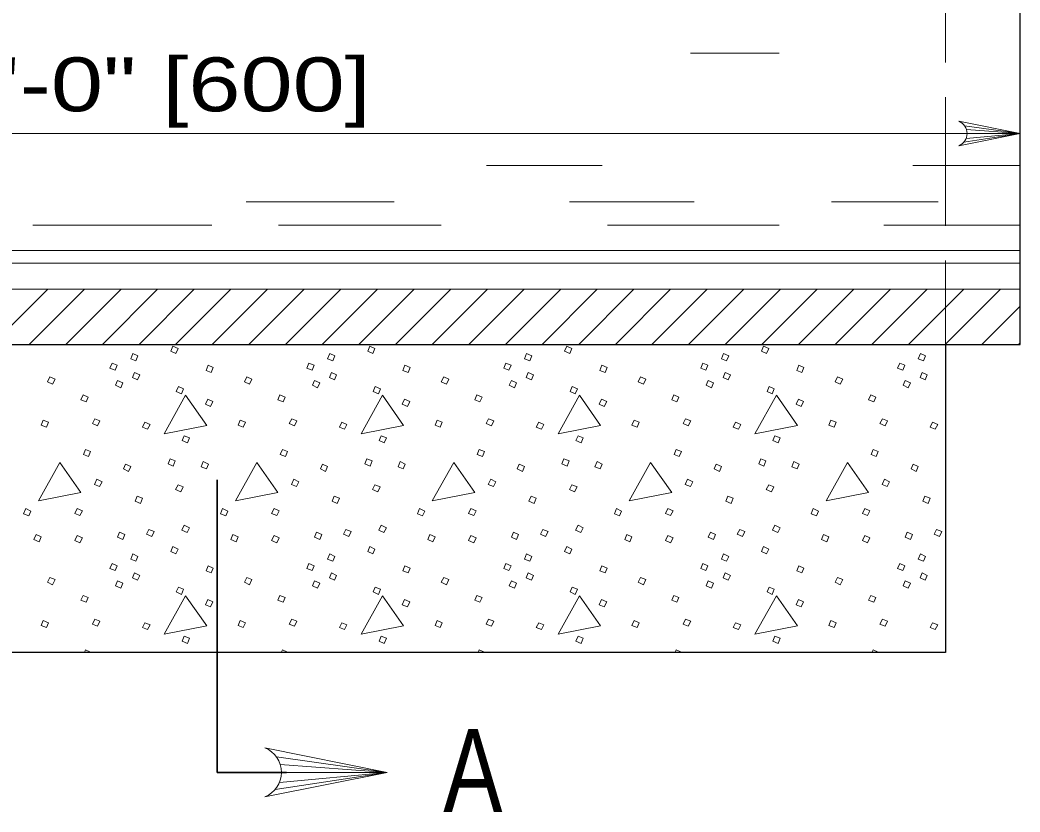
# Model space of a CAD drawing. Extents: x 1036.7 to 1070.7, y 883.9 to 905.9.
# Drawn here: x 1047.274 to 1050.167, y 893.349 to 895.639 of the extents above; entities that cross this region are included whole.
import ezdxf

# ---------------------------------------------------------------- set-up
doc = ezdxf.new("R2010")
doc.units = 0
doc.header["$LTSCALE"] = 0.062
doc.linetypes.add('LONG_DASHED', pattern=[7.5, 6, -1.5])
doc.layers.add('1', color=7, linetype='Continuous', lineweight=13)

msp = doc.modelspace()

# ---------------------------------------------------------------- linework, layer by layer
at = {"layer": '1', "linetype": 'LONG_DASHED'}
msp.add_line((1049.95158, 896.83225), (1049.95158, 894.70125), dxfattribs=at)
at = {"layer": '1', "lineweight": 25}
for p, q in [((1050.167, 894.86117), (1050.167, 896.67133)), ((1050.167, 894.70125), (1050.167, 894.86117)), ((1046.47158, 894.70125), (1050.167, 894.70125)), ((1049.95158, 894.70125), (1049.95158, 893.80992)), ((1049.00467, 893.80992), (1045.73742, 893.80992)), ((1049.95158, 893.80992), (1048.87233, 893.80992))]:
    msp.add_line(p, q, dxfattribs=at)
at = {"layer": '1'}
for p, q in [((1049.21367, 895.54308), (1049.46975, 895.54308)), ((1045.94308, 895.31108), (1048.23675, 895.31108)), ((1048.23675, 895.31108), (1050.167, 895.31108)), ((1050.00492, 895.28625), (1050.167, 895.31108)), ((1050.00675, 895.3335), (1050.167, 895.31108)), ((1050.011, 895.29667), (1050.167, 895.31108)), ((1050.01217, 895.32233), (1050.167, 895.31108)), ((1050.01383, 895.31108), (1050.167, 895.31108)), ((1048.62308, 895.2185), (1048.95758, 895.2185)), ((1049.85658, 895.2185), (1050.167, 895.2185)), ((1047.92792, 895.11383), (1048.35642, 895.11383)), ((1048.8635, 895.11383), (1049.22417, 895.11383)), ((1049.62133, 895.11383), (1049.92975, 895.11383)), ((1047.31108, 895.04575), (1047.82858, 895.04575)), ((1048.02192, 895.04575), (1048.49242, 895.04575)), ((1048.97325, 895.04575), (1049.46975, 895.04575)), ((1049.77292, 895.04575), (1050.167, 895.04575)), ((1045.94308, 894.97258), (1050.167, 894.97258)), ((1045.94308, 894.93592), (1050.167, 894.93592)), ((1050.167, 894.86117), (1045.94308, 894.86117)), ((1047.19383, 894.70125), (1047.35375, 894.86117)), ((1047.29983, 894.70125), (1047.45983, 894.86117)), ((1047.40592, 894.70125), (1047.56583, 894.86117)), ((1047.51192, 894.70125), (1047.67183, 894.86117)), ((1047.618, 894.70125), (1047.77792, 894.86117)), ((1047.72392, 894.70125), (1047.88383, 894.86117)), ((1047.82992, 894.70125), (1047.98992, 894.86117)), ((1047.936, 894.70125), (1048.09592, 894.86117)), ((1048.042, 894.70125), (1048.20192, 894.86117)), ((1048.14808, 894.70125), (1048.308, 894.86117)), ((1048.254, 894.70125), (1048.41392, 894.86117)), ((1048.36, 894.70125), (1048.52, 894.86117)), ((1048.46608, 894.70125), (1048.626, 894.86117)), ((1048.57208, 894.70125), (1048.732, 894.86117)), ((1048.67817, 894.70125), (1048.83808, 894.86117)), ((1048.78408, 894.70125), (1048.944, 894.86117)), ((1048.89008, 894.70125), (1049.05008, 894.86117)), ((1048.99617, 894.70125), (1049.15608, 894.86117)), ((1049.10217, 894.70125), (1049.26208, 894.86117)), ((1049.20825, 894.70125), (1049.36817, 894.86117)), ((1049.31417, 894.70125), (1049.47408, 894.86117)), ((1049.42017, 894.70125), (1049.58017, 894.86117)), ((1049.52625, 894.70125), (1049.68617, 894.86117)), ((1049.63225, 894.70125), (1049.79217, 894.86117)), ((1049.73833, 894.70125), (1049.89825, 894.86117)), ((1049.84425, 894.70125), (1050.00417, 894.86117)), ((1049.95025, 894.70125), (1050.11025, 894.86117)), ((1050.05633, 894.70125), (1050.167, 894.81192)), ((1050.16233, 894.70125), (1050.167, 894.70592)), ((1047.45975, 893.80992), (1047.463, 893.81742)), ((1048.02942, 893.80992), (1048.03267, 893.81742)), ((1048.59917, 893.80992), (1048.60242, 893.81742)), ((1049.16892, 893.80992), (1049.17217, 893.81742)), ((1049.73867, 893.80992), (1049.74192, 893.81742)), ((1048.0155, 893.50825), (1048.336, 893.46342)), ((1048.01167, 893.41392), (1048.336, 893.46342)), ((1048.024, 893.43467), (1048.336, 893.46342)), ((1048.02633, 893.48608), (1048.336, 893.46342)), ((1048.02967, 893.46342), (1048.336, 893.46342))]:
    msp.add_line(p, q, dxfattribs=at)
for points in [[(1049.99, 895.27567), (1050.167, 895.31108), (1049.99, 895.34642)], [(1047.463, 893.81742), (1047.47792, 893.81142), (1047.47725, 893.80992)], [(1048.03267, 893.81742), (1048.04767, 893.81142), (1048.047, 893.80992)], [(1048.60242, 893.81742), (1048.61742, 893.81142), (1048.61675, 893.80992)], [(1049.17217, 893.81742), (1049.18717, 893.81142), (1049.1865, 893.80992)], [(1049.74192, 893.81742), (1049.75692, 893.81142), (1049.75625, 893.80992)], [(1047.982, 893.39267), (1048.336, 893.46342), (1047.982, 893.53425)]]:
    msp.add_lwpolyline(points, dxfattribs=at)
for points in [[(1047.59992, 894.67492), (1047.61492, 894.66792), (1047.60892, 894.65392), (1047.59392, 894.65992)], [(1047.71583, 894.69592), (1047.73083, 894.68892), (1047.72483, 894.67492), (1047.70983, 894.68192)], [(1048.16967, 894.67492), (1048.18458, 894.66792), (1048.17858, 894.65392), (1048.16367, 894.65992)], [(1048.28558, 894.69592), (1048.30058, 894.68892), (1048.29458, 894.67492), (1048.27958, 894.68192)], [(1048.73933, 894.67492), (1048.75433, 894.66792), (1048.74833, 894.65392), (1048.73333, 894.65992)], [(1048.85533, 894.69592), (1048.87033, 894.68892), (1048.86433, 894.67492), (1048.84933, 894.68192)], [(1049.30908, 894.67492), (1049.32408, 894.66792), (1049.31808, 894.65392), (1049.30308, 894.65992)], [(1049.425, 894.69592), (1049.44, 894.68892), (1049.434, 894.67492), (1049.419, 894.68192)], [(1049.87883, 894.67492), (1049.89383, 894.66792), (1049.88783, 894.65392), (1049.87283, 894.65992)], [(1047.53992, 894.64692), (1047.55492, 894.64092), (1047.54892, 894.62692), (1047.53392, 894.63292)], [(1048.10967, 894.64692), (1048.12467, 894.64092), (1048.11867, 894.62692), (1048.10367, 894.63292)], [(1048.67942, 894.64692), (1048.69442, 894.64092), (1048.68842, 894.62692), (1048.67342, 894.63292)], [(1049.24908, 894.64692), (1049.26408, 894.64092), (1049.25808, 894.62692), (1049.24308, 894.63292)], [(1049.81883, 894.64692), (1049.83383, 894.64092), (1049.82783, 894.62692), (1049.81283, 894.63292)], [(1047.60492, 894.61992), (1047.61992, 894.61292), (1047.61392, 894.59892), (1047.59892, 894.60592)], [(1047.81783, 894.64092), (1047.83275, 894.63392), (1047.82675, 894.61992), (1047.81183, 894.62592)], [(1048.17467, 894.61992), (1048.18958, 894.61292), (1048.18358, 894.59892), (1048.16867, 894.60592)], [(1048.3875, 894.64092), (1048.4025, 894.63392), (1048.3965, 894.61992), (1048.3815, 894.62592)], [(1048.74433, 894.61992), (1048.75933, 894.61292), (1048.75333, 894.59892), (1048.73833, 894.60592)], [(1048.95725, 894.64092), (1048.97225, 894.63392), (1048.96625, 894.61992), (1048.95125, 894.62592)], [(1049.31408, 894.61992), (1049.32908, 894.61292), (1049.32308, 894.59892), (1049.30808, 894.60592)], [(1049.527, 894.64092), (1049.542, 894.63392), (1049.536, 894.61992), (1049.521, 894.62592)], [(1049.88383, 894.61992), (1049.89883, 894.61292), (1049.89283, 894.59892), (1049.87783, 894.60592)], [(1047.36, 894.60692), (1047.375, 894.60092), (1047.368, 894.586), (1047.353, 894.59292)], [(1047.55592, 894.59692), (1047.57092, 894.58992), (1047.56492, 894.576), (1047.54992, 894.583)], [(1047.92975, 894.60692), (1047.94475, 894.60092), (1047.93775, 894.586), (1047.92275, 894.59292)], [(1048.12567, 894.59692), (1048.14067, 894.58992), (1048.13467, 894.576), (1048.11967, 894.583)], [(1048.4995, 894.60692), (1048.5145, 894.60092), (1048.5075, 894.586), (1048.4925, 894.59292)], [(1048.69542, 894.59692), (1048.71033, 894.58992), (1048.70433, 894.576), (1048.68942, 894.583)], [(1049.06917, 894.60692), (1049.08417, 894.60092), (1049.07717, 894.586), (1049.06217, 894.59292)], [(1049.26508, 894.59692), (1049.28008, 894.58992), (1049.27408, 894.576), (1049.25908, 894.583)], [(1049.63892, 894.60692), (1049.65392, 894.60092), (1049.64692, 894.586), (1049.63192, 894.59292)], [(1049.83483, 894.59692), (1049.84983, 894.58992), (1049.84383, 894.576), (1049.82883, 894.583)], [(1047.73183, 894.579), (1047.74683, 894.573), (1047.74083, 894.558), (1047.72583, 894.565)], [(1048.30158, 894.579), (1048.31658, 894.573), (1048.31058, 894.558), (1048.29558, 894.565)], [(1048.87133, 894.579), (1048.88625, 894.573), (1048.88033, 894.558), (1048.86533, 894.565)], [(1049.441, 894.579), (1049.456, 894.573), (1049.45, 894.558), (1049.435, 894.565)], [(1047.456, 894.555), (1047.47092, 894.549), (1047.46492, 894.535), (1047.45, 894.541)], [(1047.75283, 894.554), (1047.69083, 894.443), (1047.81383, 894.467)], [(1047.81683, 894.543), (1047.83175, 894.536), (1047.82475, 894.522), (1047.80983, 894.528)], [(1048.02567, 894.555), (1048.04067, 894.549), (1048.03467, 894.535), (1048.01967, 894.541)], [(1048.32258, 894.554), (1048.26058, 894.443), (1048.3835, 894.467)], [(1048.3865, 894.543), (1048.4015, 894.536), (1048.3945, 894.522), (1048.3795, 894.528)], [(1048.59542, 894.555), (1048.61042, 894.549), (1048.60442, 894.535), (1048.58942, 894.541)], [(1048.89225, 894.554), (1048.83033, 894.443), (1048.95325, 894.467)], [(1048.95625, 894.543), (1048.97125, 894.536), (1048.96425, 894.522), (1048.94925, 894.528)], [(1049.16517, 894.555), (1049.18017, 894.549), (1049.17417, 894.535), (1049.15917, 894.541)], [(1049.462, 894.554), (1049.40008, 894.443), (1049.523, 894.467)], [(1049.526, 894.543), (1049.541, 894.536), (1049.534, 894.522), (1049.519, 894.528)], [(1049.73492, 894.555), (1049.74992, 894.549), (1049.74392, 894.535), (1049.72892, 894.541)], [(1047.341, 894.482), (1047.356, 894.476), (1047.35, 894.462), (1047.335, 894.468)], [(1047.48992, 894.486), (1047.50492, 894.48), (1047.49792, 894.466), (1047.48292, 894.472)], [(1047.63492, 894.476), (1047.64983, 894.47), (1047.64283, 894.456), (1047.62792, 894.462)], [(1047.91075, 894.482), (1047.92575, 894.476), (1047.91975, 894.462), (1047.90475, 894.468)], [(1048.05967, 894.486), (1048.07467, 894.48), (1048.06767, 894.466), (1048.05267, 894.472)], [(1048.20458, 894.476), (1048.21958, 894.47), (1048.21258, 894.456), (1048.19758, 894.462)], [(1048.4805, 894.482), (1048.4955, 894.476), (1048.4895, 894.462), (1048.4745, 894.468)], [(1048.62942, 894.486), (1048.64442, 894.48), (1048.63742, 894.466), (1048.62242, 894.472)], [(1048.77433, 894.476), (1048.78933, 894.47), (1048.78233, 894.456), (1048.76733, 894.462)], [(1049.05025, 894.482), (1049.06517, 894.476), (1049.05917, 894.462), (1049.04425, 894.468)], [(1049.19917, 894.486), (1049.21417, 894.48), (1049.20717, 894.466), (1049.19217, 894.472)], [(1049.34408, 894.476), (1049.35908, 894.47), (1049.35208, 894.456), (1049.33708, 894.462)], [(1049.61992, 894.482), (1049.63492, 894.476), (1049.62892, 894.462), (1049.61392, 894.468)], [(1049.76892, 894.486), (1049.78383, 894.48), (1049.77683, 894.466), (1049.76192, 894.472)], [(1049.91383, 894.476), (1049.92883, 894.47), (1049.92183, 894.456), (1049.90683, 894.462)], [(1047.74883, 894.43708), (1047.76383, 894.43108), (1047.75783, 894.41608), (1047.74283, 894.42308)], [(1048.31858, 894.43708), (1048.33358, 894.43108), (1048.32758, 894.41608), (1048.31258, 894.42308)], [(1048.88825, 894.43708), (1048.90325, 894.43108), (1048.89725, 894.41608), (1048.88225, 894.42308)], [(1049.458, 894.43708), (1049.473, 894.43108), (1049.467, 894.41608), (1049.452, 894.42308)], [(1047.463, 894.39708), (1047.47792, 894.39108), (1047.47192, 894.37708), (1047.457, 894.38308)], [(1048.03267, 894.39708), (1048.04767, 894.39108), (1048.04167, 894.37708), (1048.02667, 894.38308)], [(1048.60242, 894.39708), (1048.61742, 894.39108), (1048.61142, 894.37708), (1048.59642, 894.38308)], [(1049.17217, 894.39708), (1049.18717, 894.39108), (1049.18117, 894.37708), (1049.16617, 894.38308)], [(1049.74192, 894.39708), (1049.75692, 894.39108), (1049.75092, 894.37708), (1049.73592, 894.38308)], [(1047.389, 894.36008), (1047.327, 894.24917), (1047.45, 894.27317)], [(1047.70783, 894.37008), (1047.72283, 894.36408), (1047.71683, 894.34908), (1047.70183, 894.35608)], [(1047.80383, 894.36208), (1047.81883, 894.35508), (1047.81283, 894.34108), (1047.79783, 894.34708)], [(1047.95875, 894.36008), (1047.89675, 894.24917), (1048.01967, 894.27317)], [(1048.27758, 894.37008), (1048.29258, 894.36408), (1048.28658, 894.34908), (1048.27158, 894.35608)], [(1048.3735, 894.36208), (1048.3885, 894.35508), (1048.3825, 894.34108), (1048.3675, 894.34708)], [(1048.5285, 894.36008), (1048.4665, 894.24917), (1048.58942, 894.27317)], [(1048.84733, 894.37008), (1048.86233, 894.36408), (1048.85633, 894.34908), (1048.84133, 894.35608)], [(1048.94325, 894.36208), (1048.95825, 894.35508), (1048.95225, 894.34108), (1048.93725, 894.34708)], [(1049.09817, 894.36008), (1049.03625, 894.24917), (1049.15917, 894.27317)], [(1049.417, 894.37008), (1049.432, 894.36408), (1049.426, 894.34908), (1049.41108, 894.35608)], [(1049.513, 894.36208), (1049.528, 894.35508), (1049.522, 894.34108), (1049.507, 894.34708)], [(1049.66792, 894.36008), (1049.60592, 894.24917), (1049.72892, 894.27317)], [(1047.57892, 894.35508), (1047.59392, 894.34808), (1047.58792, 894.33408), (1047.57292, 894.34108)], [(1048.14867, 894.35508), (1048.16367, 894.34808), (1048.15767, 894.33408), (1048.14267, 894.34108)], [(1048.71833, 894.35508), (1048.73333, 894.34808), (1048.72733, 894.33408), (1048.71233, 894.34108)], [(1049.28808, 894.35508), (1049.30308, 894.34808), (1049.29708, 894.33408), (1049.28208, 894.34108)], [(1049.85783, 894.35508), (1049.87283, 894.34808), (1049.86683, 894.33408), (1049.85183, 894.34108)], [(1047.49592, 894.31108), (1047.51092, 894.30408), (1047.50392, 894.29017), (1047.48892, 894.29608)], [(1048.06567, 894.31108), (1048.08067, 894.30408), (1048.07367, 894.29017), (1048.05867, 894.29608)], [(1048.63542, 894.31108), (1048.65042, 894.30408), (1048.64342, 894.29017), (1048.62842, 894.29608)], [(1049.20517, 894.31108), (1049.22017, 894.30408), (1049.21317, 894.29017), (1049.19817, 894.29608)], [(1049.77483, 894.31108), (1049.78983, 894.30408), (1049.78283, 894.29017), (1049.76792, 894.29608)], [(1047.73083, 894.29508), (1047.74583, 894.28917), (1047.73883, 894.27517), (1047.72383, 894.28117)], [(1048.30058, 894.29508), (1048.31558, 894.28917), (1048.30858, 894.27517), (1048.29358, 894.28117)], [(1048.87033, 894.29508), (1048.88533, 894.28917), (1048.87833, 894.27517), (1048.86333, 894.28117)], [(1049.44, 894.29508), (1049.455, 894.28917), (1049.448, 894.27517), (1049.433, 894.28117)], [(1047.61292, 894.26217), (1047.62792, 894.25617), (1047.62192, 894.24117), (1047.60692, 894.24817)], [(1048.18258, 894.26217), (1048.19758, 894.25617), (1048.19158, 894.24117), (1048.17658, 894.24817)], [(1048.75233, 894.26217), (1048.76733, 894.25617), (1048.76133, 894.24117), (1048.74633, 894.24817)], [(1049.32208, 894.26217), (1049.33708, 894.25617), (1049.33108, 894.24117), (1049.31608, 894.24817)], [(1049.89183, 894.26217), (1049.90683, 894.25617), (1049.90083, 894.24117), (1049.88583, 894.24817)], [(1047.29008, 894.22617), (1047.305, 894.21917), (1047.299, 894.20517), (1047.28408, 894.21117)], [(1047.439, 894.22617), (1047.454, 894.22017), (1047.447, 894.20617), (1047.432, 894.21217)], [(1047.85975, 894.22617), (1047.87475, 894.21917), (1047.86875, 894.20517), (1047.85375, 894.21117)], [(1048.00867, 894.22617), (1048.02367, 894.22017), (1048.01667, 894.20617), (1048.00167, 894.21217)], [(1048.4295, 894.22617), (1048.4445, 894.21917), (1048.4385, 894.20517), (1048.4235, 894.21117)], [(1048.57842, 894.22617), (1048.59342, 894.22017), (1048.58642, 894.20617), (1048.57142, 894.21217)], [(1048.99925, 894.22617), (1049.01425, 894.21917), (1049.00825, 894.20517), (1048.99325, 894.21117)], [(1049.14817, 894.22617), (1049.16317, 894.22017), (1049.15617, 894.20617), (1049.14117, 894.21217)], [(1049.569, 894.22617), (1049.584, 894.21917), (1049.578, 894.20517), (1049.563, 894.21117)], [(1049.71792, 894.22617), (1049.73292, 894.22017), (1049.72592, 894.20617), (1049.71092, 894.21217)], [(1047.56192, 894.15817), (1047.57692, 894.15117), (1047.57092, 894.13725), (1047.55592, 894.14325)], [(1047.64683, 894.16617), (1047.66183, 894.16017), (1047.65483, 894.14525), (1047.63992, 894.15217)], [(1047.74883, 894.17817), (1047.76383, 894.17117), (1047.75683, 894.15717), (1047.74183, 894.16417)], [(1048.13167, 894.15817), (1048.14667, 894.15117), (1048.14067, 894.13725), (1048.12567, 894.14325)], [(1048.21658, 894.16617), (1048.23158, 894.16017), (1048.22458, 894.14525), (1048.20958, 894.15217)], [(1048.31858, 894.17817), (1048.33358, 894.17117), (1048.32658, 894.15717), (1048.31158, 894.16417)], [(1048.70142, 894.15817), (1048.71633, 894.15117), (1048.71033, 894.13725), (1048.69542, 894.14325)], [(1048.78633, 894.16617), (1048.80133, 894.16017), (1048.79433, 894.14525), (1048.77933, 894.15217)], [(1048.88825, 894.17817), (1048.90325, 894.17117), (1048.89625, 894.15717), (1048.88133, 894.16417)], [(1049.27108, 894.15817), (1049.28608, 894.15117), (1049.28008, 894.13725), (1049.26508, 894.14325)], [(1049.35608, 894.16617), (1049.37108, 894.16017), (1049.36408, 894.14525), (1049.34908, 894.15217)], [(1049.458, 894.17817), (1049.473, 894.17117), (1049.466, 894.15717), (1049.451, 894.16417)], [(1049.84083, 894.15817), (1049.85583, 894.15117), (1049.84983, 894.13725), (1049.83483, 894.14325)], [(1049.92583, 894.16617), (1049.94083, 894.16017), (1049.93383, 894.14525), (1049.91883, 894.15217)], [(1047.32, 894.15117), (1047.335, 894.14425), (1047.329, 894.13025), (1047.314, 894.13725)], [(1047.439, 894.14825), (1047.454, 894.14225), (1047.447, 894.12725), (1047.432, 894.13425)], [(1047.88975, 894.15117), (1047.90475, 894.14425), (1047.89875, 894.13025), (1047.88375, 894.13725)], [(1048.00867, 894.14825), (1048.02367, 894.14225), (1048.01667, 894.12725), (1048.00167, 894.13425)], [(1048.4595, 894.15117), (1048.4745, 894.14425), (1048.4685, 894.13025), (1048.4535, 894.13725)], [(1048.57842, 894.14825), (1048.59342, 894.14225), (1048.58642, 894.12725), (1048.57142, 894.13425)], [(1049.02925, 894.15117), (1049.04425, 894.14425), (1049.03825, 894.13025), (1049.02325, 894.13725)], [(1049.14817, 894.14825), (1049.16317, 894.14225), (1049.15617, 894.12725), (1049.14117, 894.13425)], [(1049.59892, 894.15117), (1049.61392, 894.14425), (1049.60792, 894.13025), (1049.59292, 894.13725)], [(1049.71792, 894.14825), (1049.73292, 894.14225), (1049.72592, 894.12725), (1049.71092, 894.13425)], [(1047.71583, 894.11625), (1047.73083, 894.10925), (1047.72483, 894.09525), (1047.70983, 894.10225)], [(1048.28558, 894.11625), (1048.30058, 894.10925), (1048.29458, 894.09525), (1048.27958, 894.10225)], [(1048.85533, 894.11625), (1048.87033, 894.10925), (1048.86433, 894.09525), (1048.84933, 894.10225)], [(1049.425, 894.11625), (1049.44, 894.10925), (1049.434, 894.09525), (1049.419, 894.10225)], [(1047.53992, 894.06725), (1047.55492, 894.06125), (1047.54892, 894.04725), (1047.53392, 894.05325)], [(1047.59992, 894.09525), (1047.61492, 894.08825), (1047.60892, 894.07425), (1047.59392, 894.08025)], [(1048.10967, 894.06725), (1048.12467, 894.06125), (1048.11867, 894.04725), (1048.10367, 894.05325)], [(1048.16967, 894.09525), (1048.18458, 894.08825), (1048.17858, 894.07425), (1048.16367, 894.08025)], [(1048.67942, 894.06725), (1048.69442, 894.06125), (1048.68842, 894.04725), (1048.67342, 894.05325)], [(1048.73933, 894.09525), (1048.75433, 894.08825), (1048.74833, 894.07425), (1048.73333, 894.08025)], [(1049.24908, 894.06725), (1049.26408, 894.06125), (1049.25808, 894.04725), (1049.24308, 894.05325)], [(1049.30908, 894.09525), (1049.32408, 894.08825), (1049.31808, 894.07425), (1049.30308, 894.08025)], [(1049.81883, 894.06725), (1049.83383, 894.06125), (1049.82783, 894.04725), (1049.81283, 894.05325)], [(1049.87883, 894.09525), (1049.89383, 894.08825), (1049.88783, 894.07425), (1049.87283, 894.08025)], [(1047.60492, 894.04025), (1047.61992, 894.03325), (1047.61392, 894.01925), (1047.59892, 894.02625)], [(1047.81783, 894.06125), (1047.83275, 894.05425), (1047.82675, 894.04025), (1047.81183, 894.04625)], [(1048.17467, 894.04025), (1048.18958, 894.03325), (1048.18358, 894.01925), (1048.16867, 894.02625)], [(1048.3875, 894.06125), (1048.4025, 894.05425), (1048.3965, 894.04025), (1048.3815, 894.04625)], [(1048.74433, 894.04025), (1048.75933, 894.03325), (1048.75333, 894.01925), (1048.73833, 894.02625)], [(1048.95725, 894.06125), (1048.97225, 894.05425), (1048.96625, 894.04025), (1048.95125, 894.04625)], [(1049.31408, 894.04025), (1049.32908, 894.03325), (1049.32308, 894.01925), (1049.30808, 894.02625)], [(1049.527, 894.06125), (1049.542, 894.05425), (1049.536, 894.04025), (1049.521, 894.04625)], [(1049.88383, 894.04025), (1049.89883, 894.03325), (1049.89283, 894.01925), (1049.87783, 894.02625)], [(1047.36, 894.02725), (1047.375, 894.02125), (1047.368, 894.00633), (1047.353, 894.01325)], [(1047.55592, 894.01725), (1047.57092, 894.01025), (1047.56492, 893.99633), (1047.54992, 894.00333)], [(1047.92975, 894.02725), (1047.94475, 894.02125), (1047.93775, 894.00633), (1047.92275, 894.01325)], [(1048.12567, 894.01725), (1048.14067, 894.01025), (1048.13467, 893.99633), (1048.11967, 894.00333)], [(1048.4995, 894.02725), (1048.5145, 894.02125), (1048.5075, 894.00633), (1048.4925, 894.01325)], [(1048.69542, 894.01725), (1048.71033, 894.01025), (1048.70433, 893.99633), (1048.68942, 894.00333)], [(1049.06917, 894.02725), (1049.08417, 894.02125), (1049.07717, 894.00633), (1049.06217, 894.01325)], [(1049.26508, 894.01725), (1049.28008, 894.01025), (1049.27408, 893.99633), (1049.25908, 894.00333)], [(1049.63892, 894.02725), (1049.65392, 894.02125), (1049.64692, 894.00633), (1049.63192, 894.01325)], [(1049.83483, 894.01725), (1049.84983, 894.01025), (1049.84383, 893.99633), (1049.82883, 894.00333)], [(1047.73183, 893.99933), (1047.74683, 893.99333), (1047.74083, 893.97833), (1047.72583, 893.98533)], [(1048.30158, 893.99933), (1048.31658, 893.99333), (1048.31058, 893.97833), (1048.29558, 893.98533)], [(1048.87133, 893.99933), (1048.88625, 893.99333), (1048.88033, 893.97833), (1048.86533, 893.98533)], [(1049.441, 893.99933), (1049.456, 893.99333), (1049.45, 893.97833), (1049.435, 893.98533)], [(1047.456, 893.97533), (1047.47092, 893.96933), (1047.46492, 893.95533), (1047.45, 893.96133)], [(1047.75283, 893.97433), (1047.69083, 893.86333), (1047.81383, 893.88733)], [(1047.81683, 893.96333), (1047.83175, 893.95633), (1047.82475, 893.94233), (1047.80983, 893.94833)], [(1048.02567, 893.97533), (1048.04067, 893.96933), (1048.03467, 893.95533), (1048.01967, 893.96133)], [(1048.32258, 893.97433), (1048.26058, 893.86333), (1048.3835, 893.88733)], [(1048.3865, 893.96333), (1048.4015, 893.95633), (1048.3945, 893.94233), (1048.3795, 893.94833)], [(1048.59542, 893.97533), (1048.61042, 893.96933), (1048.60442, 893.95533), (1048.58942, 893.96133)], [(1048.89225, 893.97433), (1048.83033, 893.86333), (1048.95325, 893.88733)], [(1048.95625, 893.96333), (1048.97125, 893.95633), (1048.96425, 893.94233), (1048.94925, 893.94833)], [(1049.16517, 893.97533), (1049.18017, 893.96933), (1049.17417, 893.95533), (1049.15917, 893.96133)], [(1049.462, 893.97433), (1049.40008, 893.86333), (1049.523, 893.88733)], [(1049.526, 893.96333), (1049.541, 893.95633), (1049.534, 893.94233), (1049.519, 893.94833)], [(1049.73492, 893.97533), (1049.74992, 893.96933), (1049.74392, 893.95533), (1049.72892, 893.96133)], [(1047.341, 893.90233), (1047.356, 893.89633), (1047.35, 893.88233), (1047.335, 893.88833)], [(1047.48992, 893.90633), (1047.50492, 893.90033), (1047.49792, 893.88633), (1047.48292, 893.89233)], [(1047.63492, 893.89633), (1047.64983, 893.89033), (1047.64283, 893.87633), (1047.62792, 893.88233)], [(1047.91075, 893.90233), (1047.92575, 893.89633), (1047.91975, 893.88233), (1047.90475, 893.88833)], [(1048.05967, 893.90633), (1048.07467, 893.90033), (1048.06767, 893.88633), (1048.05267, 893.89233)], [(1048.20458, 893.89633), (1048.21958, 893.89033), (1048.21258, 893.87633), (1048.19758, 893.88233)], [(1048.4805, 893.90233), (1048.4955, 893.89633), (1048.4895, 893.88233), (1048.4745, 893.88833)], [(1048.62942, 893.90633), (1048.64442, 893.90033), (1048.63742, 893.88633), (1048.62242, 893.89233)], [(1048.77433, 893.89633), (1048.78933, 893.89033), (1048.78233, 893.87633), (1048.76733, 893.88233)], [(1049.05025, 893.90233), (1049.06517, 893.89633), (1049.05917, 893.88233), (1049.04425, 893.88833)], [(1049.19917, 893.90633), (1049.21417, 893.90033), (1049.20717, 893.88633), (1049.19217, 893.89233)], [(1049.34408, 893.89633), (1049.35908, 893.89033), (1049.35208, 893.87633), (1049.33708, 893.88233)], [(1049.61992, 893.90233), (1049.63492, 893.89633), (1049.62892, 893.88233), (1049.61392, 893.88833)], [(1049.76892, 893.90633), (1049.78383, 893.90033), (1049.77683, 893.88633), (1049.76192, 893.89233)], [(1049.91383, 893.89633), (1049.92883, 893.89033), (1049.92183, 893.87633), (1049.90683, 893.88233)], [(1047.74883, 893.85742), (1047.76383, 893.85142), (1047.75783, 893.83642), (1047.74283, 893.84342)], [(1048.31858, 893.85742), (1048.33358, 893.85142), (1048.32758, 893.83642), (1048.31258, 893.84342)], [(1048.88825, 893.85742), (1048.90325, 893.85142), (1048.89725, 893.83642), (1048.88225, 893.84342)], [(1049.458, 893.85742), (1049.473, 893.85142), (1049.467, 893.83642), (1049.452, 893.84342)]]:
    msp.add_lwpolyline(points, close=True, dxfattribs=at)
at = {"layer": '1', "lineweight": 35}
msp.add_lwpolyline([(1047.8445, 894.30958), (1047.8445, 893.46342), (1048.04442, 893.46342)], dxfattribs=at)
at = {"layer": '1'}
for centre, radius in [((1049.97573, 895.31108), 0.0382), ((1047.95338, 893.46351), 0.0764)]:
    msp.add_arc(centre, radius, 292.08605, 67.91218, dxfattribs=at)

# ---------------------------------------------------------------- texts
for s, height, width, p in [('2\'-0" [600]', 0.156, 1.3, (1047.07008, 895.37517)), ('A', 0.24, 0.8, (1048.49825, 893.34892))]:
    msp.add_text(s, height=height, dxfattribs=dict(at, width=width)).set_placement(p)

doc.saveas('drawing.dxf')
